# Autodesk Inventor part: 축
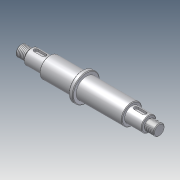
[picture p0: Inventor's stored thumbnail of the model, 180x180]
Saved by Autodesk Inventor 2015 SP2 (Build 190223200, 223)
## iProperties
Company: 한국ATC센터
Created: 2015-02
Part Number: 축
Document SubType Name: Modeling
Designer: KYOUNG IL JANG
Density: 1 g/cm^3
Material: 일반
Appearance: 기본값
Author: KYOUNG IL JANG
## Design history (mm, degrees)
sketch "스케치1"
  geometry: L1 (0, 0)-(203, 0); L2 (203, 0)-(203, 8); L3 (203, 8)-(189.5, 8); L4 (189.5, 8)-(189.5, 7); L5 (189.5, 7)-(188, 7); L6 (188, 7)-(188, 11); L7 (188, 11)-(163, 11); L8 (163, 11)-(163, 15); L9 (163, 15)-(96, 15); L10 (96, 15)-(96, 20); L11 (96, 20)-(90, 20); L12 (90, 20)-(90, 15); L13 (90, 15)-(42, 15); L14 (42, 15)-(42, 11); L15 (42, 11)-(15, 11); L16 (15, 11)-(15, 7); L17 (15, 7)-(13.5, 7); L18 (0, 8)-(0, 0); L19 (0, 8)-(13.5, 8); L20 (13.5, 8)-(13.5, 7)
  constraints: 40 end point, 16 parallel, 3 perpendicular, 1 collinear, 1 horizontal
  dimensions: "d0" = 16 diameter of L3 L1; "d1" = 14 diameter of L5 L1; "d2" = 22 diameter of L7 L1; "d3" = 30 diameter of L9 L1; "d4" = 40 diameter of L11 L1; "d5" = 16 diameter of L19 L1; "d6" = 22 diameter of L15 L1; "d8" = 1.5 distance of L16.end L17.end; "d9" = 15 distance between parallel lines of L16 L18; "d10" = 27 distance between parallel lines of L14 L16; "d11" = 48 distance between parallel lines of L12 L14; "d15" = 203 distance of L1.start L1.end; "d16" = 1.5 distance of L4.end L5.end; "d17" = 14 diameter of L17 L1; "d36" = 15 distance between parallel lines of L6 L2; "d37" = 25 distance between parallel lines of L6 L8; "d38" = 6 distance between parallel lines of L10 L12
revolve "회전1" sketch "스케치1" stored, may be unused: angle "d18" = 90 deg
feature "스레드1" dims "d19" = 10, "d20" = 0
feature "스레드2" dims "d21" = 10, "d22" = 0
chamfer "모따기1" distance "d23" = 1; stored, may be unused: second distance "d24" = 2, angle "d25" = 45 deg
node "작업 평면1"
sketch "스케치2"
  geometry: L1 (-6.5, 3)-(5.5, 3); L2 (5.5, -3)-(-6.5, -3); L3 (-13.5, -10)-(-13.5, 10) reference; L4 (140.5, 3)-(152.5, 3); L5 (152.5, -3)-(140.5, -3); L6 (159.5, 10)-(159.5, -10) reference; A1 r 3 centre (5.5, 0) between (5.5, -3) and (5.5, 3); A2 r 3 centre (-6.5, 0) between (-6.5, 3) and (-6.5, -3); A3 r 3 centre (152.5, 0) between (152.5, -3) and (152.5, 3); A4 r 3 centre (140.5, 0) between (140.5, 3) and (140.5, -3); 1 further point
  constraints: 8 end point, 8 point on circle, 8 tangent, 4 centre point, 2 horizontal, 2 horizontal alignment, 2 parallel
  dimensions: "d26" = 6 distance between parallel lines of L2 L1; "d27" = 18 dimension on A1 A2; "d28" = 4 distance edge to line of A2 L3; "d29" = 6 distance between parallel lines of L5 L4; "d30" = 18 dimension on A3 A4; "d31" = 4 distance edge to line of A3 L6
extrude "돌출1" cut sketch "스케치2" distance "d32" = 3.5; taper "d33" = 0 deg
node "솔리드1"
